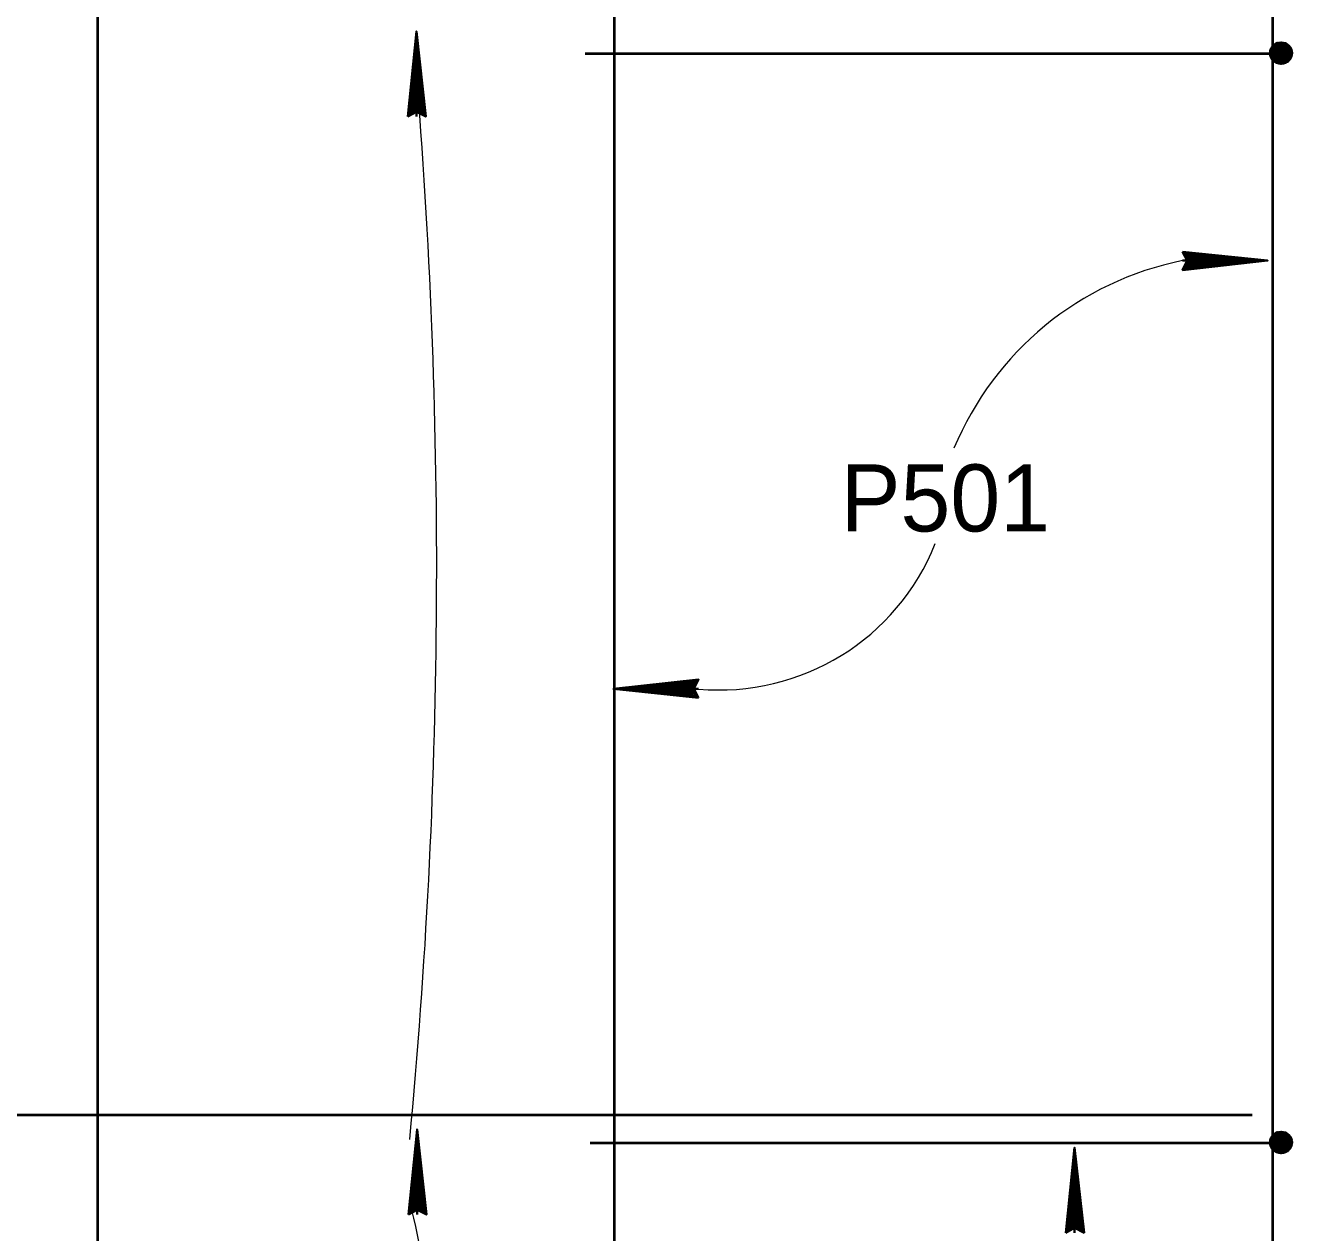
# Model space of a CAD drawing. Extents: x 4.49 to 7.69, y 0.28 to 2.27.
# Drawn here: x 5.2955 to 5.453, y 0.7638 to 0.9139 of the extents above; entities that cross this region are included whole.
import ezdxf

# ---------------------------------------------------------------- set-up
doc = ezdxf.new("R2010")
doc.units = 0
doc.header["$LTSCALE"] = 0.0033
doc.layers.add('1', color=7, linetype='Continuous', lineweight=35)

msp = doc.modelspace()

# ---------------------------------------------------------------- linework, layer by layer
at = {"layer": '1'}
for p, q in [((5.344167, 0.902583), (5.344167, 0.913167)), ((5.343167, 0.902833), (5.344083, 0.910667)), ((5.343167, 0.902833), (5.344083, 0.910667)), ((5.34325, 0.902833), (5.344083, 0.910667)), ((5.343333, 0.902833), (5.344167, 0.910667)), ((5.343333, 0.902833), (5.344333, 0.910667)), ((5.344833, 0.90275), (5.344083, 0.910083)), ((5.345, 0.902833), (5.344167, 0.910167)), ((5.345083, 0.902833), (5.344333, 0.910167)), ((5.34525, 0.902833), (5.344417, 0.910167)), ((5.439667, 0.885667), (5.4475, 0.88475)), ((5.439667, 0.885667), (5.4475, 0.88475)), ((5.439667, 0.885583), (5.4475, 0.88475)), ((5.439667, 0.8855), (5.4475, 0.884667)), ((5.439667, 0.8855), (5.4475, 0.8845)), ((5.439417, 0.884667), (5.45, 0.884667)), ((5.439583, 0.884), (5.446917, 0.88475)), ((5.439667, 0.883833), (5.447, 0.884667)), ((5.439667, 0.88375), (5.447, 0.8845)), ((5.439667, 0.883583), (5.447, 0.884417)), ((5.37925, 0.831417), (5.368667, 0.831417)), ((5.379, 0.830583), (5.371167, 0.831583)), ((5.379, 0.830583), (5.371167, 0.831417)), ((5.379, 0.830417), (5.371167, 0.831333)), ((5.379, 0.830417), (5.371167, 0.831333)), ((5.379, 0.8305), (5.371167, 0.831333)), ((5.379, 0.8325), (5.371667, 0.831667)), ((5.379, 0.832333), (5.371667, 0.831583)), ((5.379, 0.83225), (5.371667, 0.831417)), ((5.379083, 0.832083), (5.37175, 0.831333)), ((5.34425, 0.766083), (5.34425, 0.776667)), ((5.34325, 0.766333), (5.344167, 0.774167)), ((5.34325, 0.766333), (5.344167, 0.774167)), ((5.343333, 0.766333), (5.344167, 0.774167)), ((5.343417, 0.766333), (5.34425, 0.774167)), ((5.343417, 0.766333), (5.344417, 0.774167)), ((5.344917, 0.76625), (5.344167, 0.773583)), ((5.345083, 0.766333), (5.34425, 0.773667)), ((5.345167, 0.766333), (5.344417, 0.773667)), ((5.345333, 0.766333), (5.3445, 0.773667)), ((5.426, 0.763833), (5.426, 0.774417)), ((5.425, 0.764083), (5.425917, 0.771917)), ((5.425, 0.764083), (5.425917, 0.771917)), ((5.425083, 0.764083), (5.425917, 0.771917)), ((5.425167, 0.764083), (5.426, 0.771917)), ((5.425167, 0.764083), (5.426167, 0.771917)), ((5.426667, 0.764), (5.425917, 0.771333)), ((5.426833, 0.764083), (5.426, 0.771417)), ((5.426917, 0.764083), (5.426167, 0.771417)), ((5.427083, 0.764083), (5.42625, 0.771417))]:
    msp.add_line(p, q, dxfattribs=at)
at = {"layer": '1', "lineweight": 40}
for p, q in [((5.365167, 0.910417), (5.45025, 0.910417)), ((5.450583, 0.910333), (5.452583, 0.909917)), ((5.450583, 0.910083), (5.452583, 0.90975)), ((5.45075, 0.91125), (5.450667, 0.90975)), ((5.450667, 0.91075), (5.452667, 0.910417)), ((5.450667, 0.910667), (5.452667, 0.91025)), ((5.450667, 0.910583), (5.452583, 0.910167)), ((5.450667, 0.9105), (5.452583, 0.910083)), ((5.450833, 0.91125), (5.45075, 0.90975)), ((5.45075, 0.91125), (5.45275, 0.910917)), ((5.45075, 0.911167), (5.45275, 0.910833)), ((5.45075, 0.911083), (5.45275, 0.910667)), ((5.45075, 0.911), (5.45275, 0.910583)), ((5.45075, 0.910833), (5.452667, 0.9105)), ((5.450833, 0.911417), (5.45275, 0.911083)), ((5.450917, 0.91125), (5.450833, 0.90975)), ((5.451, 0.91125), (5.450917, 0.90975)), ((5.451083, 0.91125), (5.451, 0.90975)), ((5.45125, 0.91125), (5.451167, 0.90975)), ((5.451333, 0.91125), (5.45125, 0.90975)), ((5.451417, 0.91125), (5.451333, 0.90975)), ((5.4515, 0.91125), (5.451417, 0.90975)), ((5.451583, 0.91125), (5.4515, 0.90975)), ((5.451667, 0.91125), (5.451583, 0.90975)), ((5.45175, 0.91125), (5.451667, 0.90975)), ((5.451917, 0.911167), (5.45175, 0.909667)), ((5.452083, 0.911167), (5.451917, 0.909667)), ((5.452167, 0.911167), (5.452083, 0.909667)), ((5.452167, 0.911167), (5.452083, 0.909667)), ((5.45225, 0.911167), (5.452167, 0.909667)), ((5.452333, 0.911167), (5.45225, 0.909667)), ((5.452417, 0.911167), (5.452333, 0.909667)), ((5.4525, 0.911167), (5.452417, 0.909667)), ((5.452583, 0.911167), (5.4525, 0.909667)), ((5.452667, 0.911167), (5.452583, 0.909667)), ((5.452833, 0.911167), (5.45275, 0.909667)), ((5.4505, 0.909833), (5.4525, 0.9095)), ((5.450583, 0.91), (5.4525, 0.909667)), ((5.450583, 0.909917), (5.4525, 0.909583)), ((5.36575, 0.775), (5.45025, 0.775)), ((5.450583, 0.774917), (5.452583, 0.7745)), ((5.450583, 0.774667), (5.452583, 0.774333)), ((5.45075, 0.775833), (5.450667, 0.774333)), ((5.450667, 0.775333), (5.452667, 0.775)), ((5.450667, 0.77525), (5.452667, 0.774833)), ((5.450667, 0.775167), (5.452583, 0.77475)), ((5.450667, 0.775083), (5.452583, 0.774667)), ((5.450833, 0.775833), (5.45075, 0.774333)), ((5.45075, 0.775833), (5.45275, 0.7755)), ((5.45075, 0.77575), (5.45275, 0.775417)), ((5.45075, 0.775667), (5.45275, 0.77525)), ((5.45075, 0.775583), (5.45275, 0.775167)), ((5.45075, 0.775417), (5.452667, 0.775083)), ((5.450833, 0.776), (5.45275, 0.775667)), ((5.450917, 0.775833), (5.450833, 0.774333)), ((5.451, 0.775833), (5.450917, 0.774333)), ((5.451083, 0.775833), (5.451, 0.774333)), ((5.45125, 0.775833), (5.451167, 0.774333)), ((5.451333, 0.775833), (5.45125, 0.774333)), ((5.451417, 0.775833), (5.451333, 0.774333)), ((5.4515, 0.775833), (5.451417, 0.774333)), ((5.451583, 0.775833), (5.4515, 0.774333)), ((5.451667, 0.775833), (5.451583, 0.774333)), ((5.45175, 0.775833), (5.451667, 0.774333)), ((5.451917, 0.77575), (5.45175, 0.77425)), ((5.452083, 0.77575), (5.451917, 0.77425)), ((5.452167, 0.77575), (5.452083, 0.77425)), ((5.452167, 0.77575), (5.452083, 0.77425)), ((5.45225, 0.77575), (5.452167, 0.77425)), ((5.452333, 0.77575), (5.45225, 0.77425)), ((5.452417, 0.77575), (5.452333, 0.77425)), ((5.4525, 0.77575), (5.452417, 0.77425)), ((5.452583, 0.77575), (5.4525, 0.77425)), ((5.452667, 0.77575), (5.452583, 0.77425)), ((5.452833, 0.77575), (5.45275, 0.77425)), ((5.4505, 0.774417), (5.4525, 0.774083)), ((5.450583, 0.774583), (5.4525, 0.77425)), ((5.450583, 0.7745), (5.4525, 0.774167))]:
    msp.add_line(p, q, dxfattribs=at)
for points in [[(5.298583, 0.998333), (5.298583, 0.955), (5.3045, 0.949083), (5.3045, 0.74075), (5.298583, 0.734833), (5.298583, 0.688583)], [(5.362833, 0.998333), (5.362833, 0.955), (5.36875, 0.949083), (5.36875, 0.74075), (5.362833, 0.734833), (5.362833, 0.688583)], [(5.444667, 0.9985), (5.444667, 0.955167), (5.450583, 0.94925), (5.450583, 0.740917), (5.444667, 0.735), (5.444667, 0.68875)], [(5.450333, 0.910417), (5.452917, 0.91075), (5.450583, 0.91125), (5.452917, 0.910167), (5.4505, 0.90975), (5.4525, 0.909417), (5.4525, 0.9115), (5.451583, 0.909167), (5.451833, 0.91175), (5.450833, 0.909417), (5.451167, 0.91175), (5.452, 0.909167), (5.450417, 0.910917), (5.452833, 0.911083), (5.451167, 0.90925), (5.45225, 0.911667), (5.450583, 0.91125), (5.4505, 0.90975), (5.451583, 0.909167), (5.4525, 0.909417), (5.452917, 0.910167), (5.452833, 0.911083), (5.45225, 0.911667), (5.451583, 0.910583), (5.45275, 0.909667), (5.450833, 0.909417), (5.451583, 0.910583), (5.4505, 0.911083), (5.4515, 0.91175), (5.451583, 0.910667), (5.452417, 0.909417), (5.450417, 0.910667), (5.45175, 0.911), (5.4525, 0.9115)], [(4.897167, 0.7785), (5.122333, 0.7785), (5.448083, 0.7785)], [(5.450333, 0.775), (5.452917, 0.775333), (5.450583, 0.775833), (5.452917, 0.77475), (5.4505, 0.774333), (5.4525, 0.774), (5.4525, 0.776083), (5.451583, 0.77375), (5.451833, 0.776333), (5.450833, 0.774), (5.451167, 0.776333), (5.452, 0.77375), (5.450417, 0.7755), (5.452833, 0.775667), (5.451167, 0.773833), (5.45225, 0.77625), (5.450583, 0.775833), (5.4505, 0.774333), (5.451583, 0.77375), (5.4525, 0.774), (5.452917, 0.77475), (5.452833, 0.775667), (5.45225, 0.77625), (5.451583, 0.775167), (5.45275, 0.77425), (5.450833, 0.774), (5.451583, 0.775167), (5.4505, 0.775667), (5.4515, 0.776333), (5.451583, 0.77525), (5.452417, 0.774), (5.450417, 0.77525), (5.45175, 0.775583), (5.4525, 0.776083)]]:
    msp.add_lwpolyline(points, dxfattribs=at)
at = {"layer": '1'}
for points in [[(5.343083, 0.902583), (5.344167, 0.913167), (5.345333, 0.902583), (5.344167, 0.903167)], [(5.344083, 0.903333), (5.344, 0.908), (5.344083, 0.908), (5.344083, 0.907083), (5.344, 0.903333), (5.343917, 0.906333), (5.343833, 0.903167), (5.34375, 0.905417), (5.343667, 0.903167), (5.343917, 0.906667), (5.344083, 0.911333), (5.344333, 0.910417), (5.344333, 0.911667), (5.344333, 0.903333), (5.3445, 0.90575), (5.3445, 0.903167), (5.344083, 0.9085), (5.34475, 0.903167)], [(5.439417, 0.88575), (5.45, 0.884667), (5.439417, 0.8835), (5.44, 0.884667)], [(5.440167, 0.88475), (5.444833, 0.884833), (5.444833, 0.88475), (5.443917, 0.88475), (5.440167, 0.884833), (5.443167, 0.884917), (5.44, 0.885), (5.44225, 0.885083), (5.44, 0.885167), (5.4435, 0.884917), (5.448167, 0.88475), (5.44725, 0.8845), (5.4485, 0.8845), (5.440167, 0.8845), (5.442583, 0.884333), (5.44, 0.884333), (5.445333, 0.88475), (5.44, 0.884083)], [(5.37925, 0.830333), (5.368667, 0.831417), (5.37925, 0.832583), (5.378667, 0.831417)], [(5.3785, 0.831333), (5.373833, 0.83125), (5.373833, 0.831333), (5.37475, 0.831333), (5.3785, 0.83125), (5.3755, 0.831167), (5.378667, 0.831083), (5.376417, 0.831), (5.378667, 0.830917), (5.375167, 0.831167), (5.3705, 0.831333), (5.371417, 0.831583), (5.370167, 0.831583), (5.3785, 0.831583), (5.376083, 0.83175), (5.378667, 0.83175), (5.373333, 0.831333), (5.378667, 0.832)], [(5.343167, 0.766083), (5.34425, 0.776667), (5.345417, 0.766083), (5.34425, 0.766667)], [(5.344167, 0.766833), (5.344083, 0.7715), (5.344167, 0.7715), (5.344167, 0.770583), (5.344083, 0.766833), (5.344, 0.769833), (5.343917, 0.766667), (5.343833, 0.768917), (5.34375, 0.766667), (5.344, 0.770167), (5.344167, 0.774833), (5.344417, 0.773917), (5.344417, 0.775167), (5.344417, 0.766833), (5.344583, 0.76925), (5.344583, 0.766667), (5.344167, 0.772), (5.344833, 0.766667)], [(5.424917, 0.763833), (5.426, 0.774417), (5.427167, 0.763833), (5.426, 0.764417)], [(5.425917, 0.764583), (5.425833, 0.76925), (5.425917, 0.76925), (5.425917, 0.768333), (5.425833, 0.764583), (5.42575, 0.767583), (5.425667, 0.764417), (5.425583, 0.766667), (5.4255, 0.764417), (5.42575, 0.767917), (5.425917, 0.772583), (5.426167, 0.771667), (5.426167, 0.772917), (5.426167, 0.764583), (5.426333, 0.767), (5.426333, 0.764417), (5.425917, 0.76975), (5.426583, 0.764417)]]:
    msp.add_lwpolyline(points, close=True, dxfattribs=at)
for points in [[(5.344083, 0.903333), (5.343333, 0.902917), (5.343583, 0.903167), (5.343917, 0.903333), (5.343833, 0.903583), (5.3435, 0.903417), (5.34425, 0.90325), (5.34475, 0.903083), (5.345167, 0.902833)], [(5.440167, 0.88475), (5.43975, 0.8855), (5.44, 0.88525), (5.440167, 0.884917), (5.440417, 0.885), (5.44025, 0.885333), (5.440083, 0.884583), (5.439917, 0.884083), (5.439667, 0.883667)], [(5.3785, 0.831333), (5.378917, 0.830583), (5.378667, 0.830833), (5.3785, 0.831167), (5.37825, 0.831083), (5.378417, 0.83075), (5.378583, 0.8315), (5.37875, 0.832), (5.379, 0.832417)], [(5.344167, 0.766833), (5.343417, 0.766417), (5.343667, 0.766667), (5.344, 0.766833), (5.343917, 0.767083), (5.343583, 0.766917), (5.344333, 0.76675), (5.344833, 0.766583), (5.34525, 0.766333)], [(5.425917, 0.764583), (5.425167, 0.764167), (5.425417, 0.764417), (5.42575, 0.764583), (5.425667, 0.764833), (5.425333, 0.764667), (5.426083, 0.7645), (5.426583, 0.764333), (5.427, 0.764083)]]:
    msp.add_lwpolyline(points, dxfattribs=at)
at = {"layer": '1', "lineweight": 40}
for centre in [(5.451667, 0.910467), (5.451667, 0.77505)]:
    msp.add_circle(centre, 0.00132, dxfattribs=at)
at = {"layer": '1', "lineweight": 13}
for centre, radius, start, end in [((4.59422, 0.846363), 0.752466, 354.58985, 4.45032), ((5.447109, 0.846329), 0.039102, 101.34497, 157.43485), ((5.38187, 0.860123), 0.028826, 264.78548, 338.37517), ((5.282122, 0.751083), 0.063418, 344.84139, 15.15861)]:
    msp.add_arc(centre, radius, start, end, dxfattribs=at)

# ---------------------------------------------------------------- texts
at = {"layer": '1'}
msp.add_text('P501', height=0.008334, dxfattribs=at).set_placement((5.396917, 0.851))

doc.saveas('drawing.dxf')
